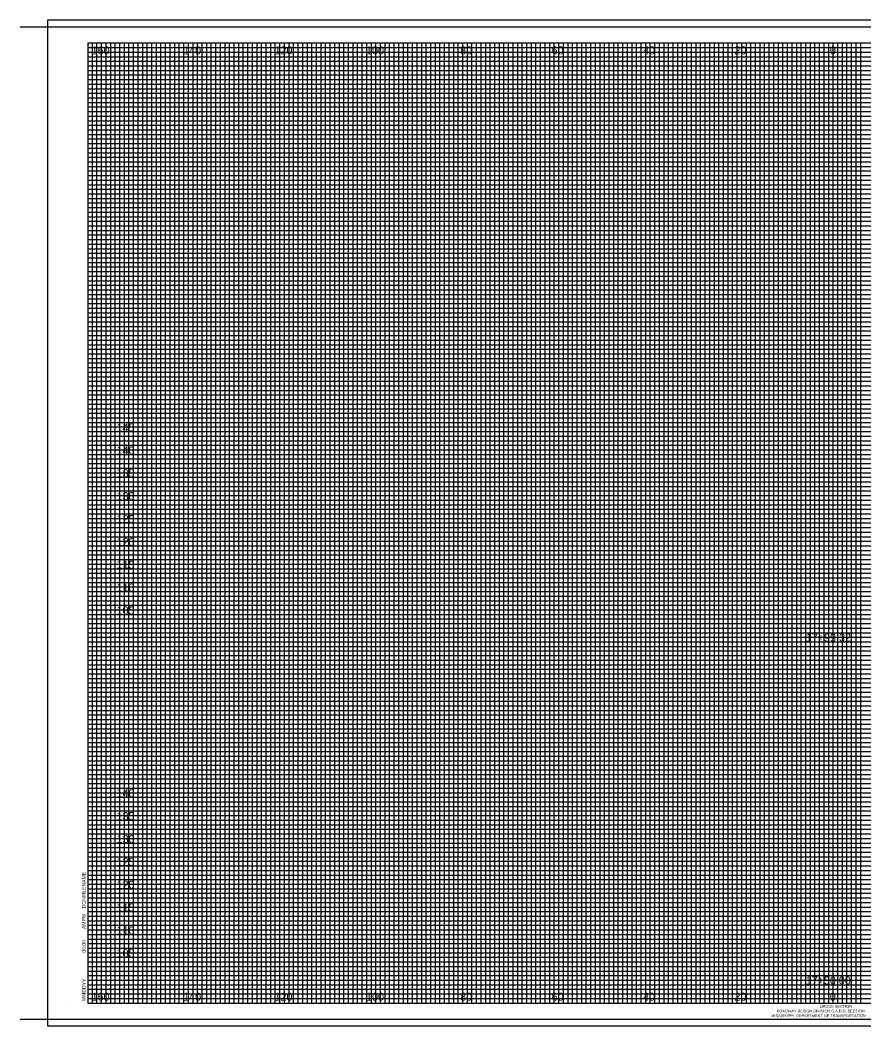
# Model space of a CAD drawing. Extents: x 21281 to 21817, y 6470 to 8300.
# Drawn here: x 21465 to 21649.5, y 8079.8 to 8299.8 of the extents above; entities that cross this region are included whole.
import ezdxf

# ---------------------------------------------------------------- set-up
doc = ezdxf.new("R2010")
doc.units = 0
for name, color, linetype in [('SHEET_BORDER', 7, 'Continuous'), ('SHEET_BORDER_TX', 7, 'Continuous'), ('SHEET_DATE_DGN_TX', 7, 'Continuous'), ('SHEET_PLOTTING_SHAPE', 7, 'Continuous'), ('XS_SHEET_LABELS_ELEVATION', 7, 'Continuous'), ('XS_SHEET_LABELS_OFFSET', 7, 'Continuous'), ('XS_SHEET_LABELS_STATION', 7, 'Continuous'), ('XS_SHEET_MAJOR_GRIDS', 7, 'Continuous'), ('XS_SHEET_MEDIUM_GRIDS', 7, 'Continuous'), ('XS_SHEET_MINOR_GRIDS', 7, 'Continuous')]:
    doc.layers.add(name, color=color, linetype=linetype)

msp = doc.modelspace()

# ---------------------------------------------------------------- linework, layer by layer
at = {"layer": 'SHEET_BORDER'}
for p, q in [((21465.04, 8298.34), (21817.04, 8298.34)), ((21479.84, 8294.84), (21814.84, 8294.84)), ((21479.84, 8294.84), (21479.84, 8084.84)), ((21623.84, 8084.84), (21623.84, 8294.84)), ((21474.84, 8084.84), (21474.84, 8084.84)), ((21479.84, 8084.84), (21814.84, 8084.84)), ((21465.04, 8081.34), (21817.04, 8081.34))]:
    msp.add_line(p, q, dxfattribs=at)
at = {"layer": 'SHEET_PLOTTING_SHAPE'}
msp.add_lwpolyline([(21471.04, 8079.84), (21817.04, 8079.84), (21817.04, 8299.84), (21471.04, 8299.84)], close=True, dxfattribs=at)
at = {"layer": 'XS_SHEET_MAJOR_GRIDS'}
for p, q in [((21484.84, 8084.84), (21484.84, 8294.84)), ((21494.84, 8084.84), (21494.84, 8294.84)), ((21504.84, 8084.84), (21504.84, 8294.84)), ((21514.84, 8084.84), (21514.84, 8294.84)), ((21524.84, 8084.84), (21524.84, 8294.84)), ((21534.84, 8084.84), (21534.84, 8294.84)), ((21544.84, 8084.84), (21544.84, 8294.84)), ((21554.84, 8084.84), (21554.84, 8294.84)), ((21564.84, 8084.84), (21564.84, 8294.84)), ((21574.84, 8084.84), (21574.84, 8294.84)), ((21584.84, 8084.84), (21584.84, 8294.84)), ((21594.84, 8084.84), (21594.84, 8294.84)), ((21604.84, 8084.84), (21604.84, 8294.84)), ((21614.84, 8084.84), (21614.84, 8294.84)), ((21624.84, 8084.84), (21624.84, 8294.84)), ((21634.84, 8084.84), (21634.84, 8294.84)), ((21644.84, 8084.84), (21644.84, 8294.84)), ((21479.84, 8284.84), (21814.84, 8284.84)), ((21479.84, 8274.84), (21814.84, 8274.84)), ((21479.84, 8264.84), (21814.84, 8264.84)), ((21479.84, 8254.84), (21814.84, 8254.84)), ((21479.84, 8244.84), (21814.84, 8244.84)), ((21479.84, 8234.84), (21814.84, 8234.84)), ((21479.84, 8224.84), (21814.84, 8224.84)), ((21479.84, 8214.84), (21814.84, 8214.84)), ((21479.84, 8204.84), (21814.84, 8204.84)), ((21479.84, 8194.84), (21814.84, 8194.84)), ((21479.84, 8184.84), (21814.84, 8184.84)), ((21479.84, 8174.84), (21814.84, 8174.84)), ((21479.84, 8164.84), (21814.84, 8164.84)), ((21479.84, 8154.84), (21814.84, 8154.84)), ((21479.84, 8144.84), (21814.84, 8144.84)), ((21479.84, 8134.84), (21814.84, 8134.84)), ((21479.84, 8124.84), (21814.84, 8124.84)), ((21479.84, 8114.84), (21814.84, 8114.84)), ((21479.84, 8104.84), (21814.84, 8104.84)), ((21479.84, 8094.84), (21814.84, 8094.84))]:
    msp.add_line(p, q, dxfattribs=at)
at = {"layer": 'XS_SHEET_MEDIUM_GRIDS'}
for p, q in [((21489.84, 8084.84), (21489.84, 8294.84)), ((21499.84, 8084.84), (21499.84, 8294.84)), ((21509.84, 8084.84), (21509.84, 8294.84)), ((21519.84, 8084.84), (21519.84, 8294.84)), ((21529.84, 8084.84), (21529.84, 8294.84)), ((21539.84, 8084.84), (21539.84, 8294.84)), ((21549.84, 8084.84), (21549.84, 8294.84)), ((21559.84, 8084.84), (21559.84, 8294.84)), ((21569.84, 8084.84), (21569.84, 8294.84)), ((21579.84, 8084.84), (21579.84, 8294.84)), ((21589.84, 8084.84), (21589.84, 8294.84)), ((21599.84, 8084.84), (21599.84, 8294.84)), ((21609.84, 8084.84), (21609.84, 8294.84)), ((21619.84, 8084.84), (21619.84, 8294.84)), ((21629.84, 8084.84), (21629.84, 8294.84)), ((21639.84, 8084.84), (21639.84, 8294.84)), ((21479.84, 8289.84), (21787.84, 8289.84)), ((21479.84, 8279.84), (21814.84, 8279.84)), ((21479.84, 8269.84), (21814.84, 8269.84)), ((21479.84, 8259.84), (21814.84, 8259.84)), ((21479.84, 8249.84), (21814.84, 8249.84)), ((21479.84, 8239.84), (21814.84, 8239.84)), ((21479.84, 8229.84), (21814.84, 8229.84)), ((21479.84, 8219.84), (21814.84, 8219.84)), ((21479.84, 8209.84), (21814.84, 8209.84)), ((21479.84, 8199.84), (21814.84, 8199.84)), ((21479.84, 8189.84), (21814.84, 8189.84)), ((21479.84, 8179.84), (21814.84, 8179.84)), ((21479.84, 8169.84), (21814.84, 8169.84)), ((21479.84, 8159.84), (21814.84, 8159.84)), ((21479.84, 8149.84), (21814.84, 8149.84)), ((21479.84, 8139.84), (21814.84, 8139.84)), ((21479.84, 8129.84), (21814.84, 8129.84)), ((21479.84, 8119.84), (21814.84, 8119.84)), ((21479.84, 8109.84), (21814.84, 8109.84)), ((21479.84, 8099.84), (21814.84, 8099.84)), ((21479.84, 8089.84), (21804.84, 8089.84))]:
    msp.add_line(p, q, dxfattribs=at)
at = {"layer": 'XS_SHEET_MINOR_GRIDS'}
for p, q in [((21480.84, 8084.84), (21480.84, 8294.84)), ((21481.84, 8084.84), (21481.84, 8294.84)), ((21482.84, 8084.84), (21482.84, 8294.84)), ((21483.84, 8084.84), (21483.84, 8294.84)), ((21485.84, 8084.84), (21485.84, 8294.84)), ((21486.84, 8084.84), (21486.84, 8294.84)), ((21487.84, 8084.84), (21487.84, 8294.84)), ((21488.84, 8084.84), (21488.84, 8294.84)), ((21490.84, 8084.84), (21490.84, 8294.84)), ((21491.84, 8084.84), (21491.84, 8294.84)), ((21492.84, 8084.84), (21492.84, 8294.84)), ((21493.84, 8084.84), (21493.84, 8294.84)), ((21495.84, 8084.84), (21495.84, 8294.84)), ((21496.84, 8084.84), (21496.84, 8294.84)), ((21497.84, 8084.84), (21497.84, 8294.84)), ((21498.84, 8084.84), (21498.84, 8294.84)), ((21500.84, 8084.84), (21500.84, 8294.84)), ((21501.84, 8084.84), (21501.84, 8294.84)), ((21502.84, 8084.84), (21502.84, 8294.84)), ((21503.84, 8084.84), (21503.84, 8294.84)), ((21505.84, 8084.84), (21505.84, 8294.84)), ((21506.84, 8084.84), (21506.84, 8294.84)), ((21507.84, 8084.84), (21507.84, 8294.84)), ((21508.84, 8084.84), (21508.84, 8294.84)), ((21510.84, 8084.84), (21510.84, 8294.84)), ((21511.84, 8084.84), (21511.84, 8294.84)), ((21512.84, 8084.84), (21512.84, 8294.84)), ((21513.84, 8084.84), (21513.84, 8294.84)), ((21515.84, 8084.84), (21515.84, 8294.84)), ((21516.84, 8084.84), (21516.84, 8294.84)), ((21517.84, 8084.84), (21517.84, 8294.84)), ((21518.84, 8084.84), (21518.84, 8294.84)), ((21520.84, 8084.84), (21520.84, 8294.84)), ((21521.84, 8084.84), (21521.84, 8294.84)), ((21522.84, 8084.84), (21522.84, 8294.84)), ((21523.84, 8084.84), (21523.84, 8294.84)), ((21525.84, 8084.84), (21525.84, 8294.84)), ((21526.84, 8084.84), (21526.84, 8294.84)), ((21527.84, 8084.84), (21527.84, 8294.84)), ((21528.84, 8084.84), (21528.84, 8294.84)), ((21530.84, 8084.84), (21530.84, 8294.84)), ((21531.84, 8084.84), (21531.84, 8294.84)), ((21532.84, 8084.84), (21532.84, 8294.84)), ((21533.84, 8084.84), (21533.84, 8294.84)), ((21535.84, 8084.84), (21535.84, 8294.84)), ((21536.84, 8084.84), (21536.84, 8294.84)), ((21537.84, 8084.84), (21537.84, 8294.84)), ((21538.84, 8084.84), (21538.84, 8294.84)), ((21540.84, 8084.84), (21540.84, 8294.84)), ((21541.84, 8084.84), (21541.84, 8294.84)), ((21542.84, 8084.84), (21542.84, 8294.84)), ((21543.84, 8084.84), (21543.84, 8294.84)), ((21545.84, 8084.84), (21545.84, 8294.84)), ((21546.84, 8084.84), (21546.84, 8294.84)), ((21547.84, 8084.84), (21547.84, 8294.84)), ((21548.84, 8084.84), (21548.84, 8294.84)), ((21550.84, 8084.84), (21550.84, 8294.84)), ((21551.84, 8084.84), (21551.84, 8294.84)), ((21552.84, 8084.84), (21552.84, 8294.84)), ((21553.84, 8084.84), (21553.84, 8294.84)), ((21555.84, 8084.84), (21555.84, 8294.84)), ((21556.84, 8084.84), (21556.84, 8294.84)), ((21557.84, 8084.84), (21557.84, 8294.84)), ((21558.84, 8084.84), (21558.84, 8294.84)), ((21560.84, 8084.84), (21560.84, 8294.84)), ((21561.84, 8084.84), (21561.84, 8294.84)), ((21562.84, 8084.84), (21562.84, 8294.84)), ((21563.84, 8084.84), (21563.84, 8294.84)), ((21565.84, 8084.84), (21565.84, 8294.84)), ((21566.84, 8084.84), (21566.84, 8294.84)), ((21567.84, 8084.84), (21567.84, 8294.84)), ((21568.84, 8084.84), (21568.84, 8294.84)), ((21570.84, 8084.84), (21570.84, 8294.84)), ((21571.84, 8084.84), (21571.84, 8294.84)), ((21572.84, 8084.84), (21572.84, 8294.84)), ((21573.84, 8084.84), (21573.84, 8294.84)), ((21575.84, 8084.84), (21575.84, 8294.84)), ((21576.84, 8084.84), (21576.84, 8294.84)), ((21577.84, 8084.84), (21577.84, 8294.84)), ((21578.84, 8084.84), (21578.84, 8294.84)), ((21580.84, 8084.84), (21580.84, 8294.84)), ((21581.84, 8084.84), (21581.84, 8294.84)), ((21582.84, 8084.84), (21582.84, 8294.84)), ((21583.84, 8084.84), (21583.84, 8294.84)), ((21585.84, 8084.84), (21585.84, 8294.84)), ((21586.84, 8084.84), (21586.84, 8294.84)), ((21587.84, 8084.84), (21587.84, 8294.84)), ((21588.84, 8084.84), (21588.84, 8294.84)), ((21590.84, 8084.84), (21590.84, 8294.84)), ((21591.84, 8084.84), (21591.84, 8294.84)), ((21592.84, 8084.84), (21592.84, 8294.84)), ((21593.84, 8084.84), (21593.84, 8294.84)), ((21595.84, 8084.84), (21595.84, 8294.84)), ((21596.84, 8084.84), (21596.84, 8294.84)), ((21597.84, 8084.84), (21597.84, 8294.84)), ((21598.84, 8084.84), (21598.84, 8294.84)), ((21600.84, 8084.84), (21600.84, 8294.84)), ((21601.84, 8084.84), (21601.84, 8294.84)), ((21602.84, 8084.84), (21602.84, 8294.84)), ((21603.84, 8084.84), (21603.84, 8294.84)), ((21605.84, 8084.84), (21605.84, 8294.84)), ((21606.84, 8084.84), (21606.84, 8294.84)), ((21607.84, 8084.84), (21607.84, 8294.84)), ((21608.84, 8084.84), (21608.84, 8294.84)), ((21610.84, 8084.84), (21610.84, 8294.84)), ((21611.84, 8084.84), (21611.84, 8294.84)), ((21612.84, 8084.84), (21612.84, 8294.84)), ((21613.84, 8084.84), (21613.84, 8294.84)), ((21615.84, 8084.84), (21615.84, 8294.84)), ((21616.84, 8084.84), (21616.84, 8294.84)), ((21617.84, 8084.84), (21617.84, 8294.84)), ((21618.84, 8084.84), (21618.84, 8294.84)), ((21620.84, 8084.84), (21620.84, 8294.84)), ((21621.84, 8084.84), (21621.84, 8294.84)), ((21622.84, 8084.84), (21622.84, 8294.84)), ((21625.84, 8084.84), (21625.84, 8294.84)), ((21626.84, 8084.84), (21626.84, 8294.84)), ((21627.84, 8084.84), (21627.84, 8294.84)), ((21628.84, 8084.84), (21628.84, 8294.84)), ((21630.84, 8084.84), (21630.84, 8294.84)), ((21631.84, 8084.84), (21631.84, 8294.84)), ((21632.84, 8084.84), (21632.84, 8294.84)), ((21633.84, 8084.84), (21633.84, 8294.84)), ((21635.84, 8084.84), (21635.84, 8294.84)), ((21636.84, 8084.84), (21636.84, 8294.84)), ((21637.84, 8084.84), (21637.84, 8294.84)), ((21638.84, 8084.84), (21638.84, 8294.84)), ((21640.84, 8084.84), (21640.84, 8294.84)), ((21641.84, 8084.84), (21641.84, 8294.84)), ((21642.84, 8084.84), (21642.84, 8294.84)), ((21643.84, 8084.84), (21643.84, 8294.84)), ((21645.84, 8084.84), (21645.84, 8294.84)), ((21646.84, 8084.84), (21646.84, 8294.84)), ((21647.84, 8084.84), (21647.84, 8294.84)), ((21648.84, 8084.84), (21648.84, 8294.84)), ((21479.84, 8293.84), (21787.84, 8293.84)), ((21479.84, 8292.84), (21787.84, 8292.84)), ((21479.84, 8291.84), (21787.84, 8291.84)), ((21479.84, 8290.84), (21787.84, 8290.84)), ((21479.84, 8288.84), (21787.84, 8288.84)), ((21479.84, 8287.84), (21787.84, 8287.84)), ((21479.84, 8286.84), (21787.84, 8286.84)), ((21479.84, 8285.84), (21814.84, 8285.84)), ((21479.84, 8283.84), (21814.84, 8283.84)), ((21479.84, 8282.84), (21814.84, 8282.84)), ((21479.84, 8281.84), (21814.84, 8281.84)), ((21479.84, 8280.84), (21814.84, 8280.84)), ((21479.84, 8278.84), (21814.84, 8278.84)), ((21479.84, 8277.84), (21814.84, 8277.84)), ((21479.84, 8276.84), (21814.84, 8276.84)), ((21479.84, 8275.84), (21814.84, 8275.84)), ((21479.84, 8273.84), (21814.84, 8273.84)), ((21479.84, 8272.84), (21814.84, 8272.84)), ((21479.84, 8271.84), (21814.84, 8271.84)), ((21479.84, 8270.84), (21814.84, 8270.84)), ((21479.84, 8268.84), (21814.84, 8268.84)), ((21479.84, 8267.84), (21814.84, 8267.84)), ((21479.84, 8266.84), (21814.84, 8266.84)), ((21479.84, 8265.84), (21814.84, 8265.84)), ((21479.84, 8263.84), (21814.84, 8263.84)), ((21479.84, 8262.84), (21814.84, 8262.84)), ((21479.84, 8261.84), (21814.84, 8261.84)), ((21479.84, 8260.84), (21814.84, 8260.84)), ((21479.84, 8258.84), (21814.84, 8258.84)), ((21479.84, 8257.84), (21814.84, 8257.84)), ((21479.84, 8256.84), (21814.84, 8256.84)), ((21479.84, 8255.84), (21814.84, 8255.84)), ((21479.84, 8253.84), (21814.84, 8253.84)), ((21479.84, 8252.84), (21814.84, 8252.84)), ((21479.84, 8251.84), (21814.84, 8251.84)), ((21479.84, 8250.84), (21814.84, 8250.84)), ((21479.84, 8248.84), (21814.84, 8248.84)), ((21479.84, 8247.84), (21814.84, 8247.84)), ((21479.84, 8246.84), (21814.84, 8246.84)), ((21479.84, 8245.84), (21814.84, 8245.84)), ((21479.84, 8243.84), (21814.84, 8243.84)), ((21479.84, 8242.84), (21814.84, 8242.84)), ((21479.84, 8241.84), (21814.84, 8241.84)), ((21479.84, 8240.84), (21814.84, 8240.84)), ((21479.84, 8238.84), (21814.84, 8238.84)), ((21479.84, 8237.84), (21814.84, 8237.84)), ((21479.84, 8236.84), (21814.84, 8236.84)), ((21479.84, 8235.84), (21814.84, 8235.84)), ((21479.84, 8233.84), (21814.84, 8233.84)), ((21479.84, 8232.84), (21814.84, 8232.84)), ((21479.84, 8231.84), (21814.84, 8231.84)), ((21479.84, 8230.84), (21814.84, 8230.84)), ((21479.84, 8228.84), (21814.84, 8228.84)), ((21479.84, 8227.84), (21814.84, 8227.84)), ((21479.84, 8226.84), (21814.84, 8226.84)), ((21479.84, 8225.84), (21814.84, 8225.84)), ((21479.84, 8223.84), (21814.84, 8223.84)), ((21479.84, 8222.84), (21814.84, 8222.84)), ((21479.84, 8221.84), (21814.84, 8221.84)), ((21479.84, 8220.84), (21814.84, 8220.84)), ((21479.84, 8218.84), (21814.84, 8218.84)), ((21479.84, 8217.84), (21814.84, 8217.84)), ((21479.84, 8216.84), (21814.84, 8216.84)), ((21479.84, 8215.84), (21814.84, 8215.84)), ((21479.84, 8213.84), (21814.84, 8213.84)), ((21479.84, 8212.84), (21814.84, 8212.84)), ((21479.84, 8211.84), (21814.84, 8211.84)), ((21479.84, 8210.84), (21814.84, 8210.84)), ((21479.84, 8208.84), (21814.84, 8208.84)), ((21479.84, 8207.84), (21814.84, 8207.84)), ((21479.84, 8206.84), (21814.84, 8206.84)), ((21479.84, 8205.84), (21814.84, 8205.84)), ((21479.84, 8203.84), (21814.84, 8203.84)), ((21479.84, 8202.84), (21814.84, 8202.84)), ((21479.84, 8201.84), (21814.84, 8201.84)), ((21479.84, 8200.84), (21814.84, 8200.84)), ((21479.84, 8198.84), (21814.84, 8198.84)), ((21479.84, 8197.84), (21814.84, 8197.84)), ((21479.84, 8196.84), (21814.84, 8196.84)), ((21479.84, 8195.84), (21814.84, 8195.84)), ((21479.84, 8193.84), (21814.84, 8193.84)), ((21479.84, 8192.84), (21814.84, 8192.84)), ((21479.84, 8191.84), (21814.84, 8191.84)), ((21479.84, 8190.84), (21814.84, 8190.84)), ((21479.84, 8188.84), (21814.84, 8188.84)), ((21479.84, 8187.84), (21814.84, 8187.84)), ((21479.84, 8186.84), (21814.84, 8186.84)), ((21479.84, 8185.84), (21814.84, 8185.84)), ((21479.84, 8183.84), (21814.84, 8183.84)), ((21479.84, 8182.84), (21814.84, 8182.84)), ((21479.84, 8181.84), (21814.84, 8181.84)), ((21479.84, 8180.84), (21814.84, 8180.84)), ((21479.84, 8178.84), (21814.84, 8178.84)), ((21479.84, 8177.84), (21814.84, 8177.84)), ((21479.84, 8176.84), (21814.84, 8176.84)), ((21479.84, 8175.84), (21814.84, 8175.84)), ((21479.84, 8173.84), (21814.84, 8173.84)), ((21479.84, 8172.84), (21814.84, 8172.84)), ((21479.84, 8171.84), (21814.84, 8171.84)), ((21479.84, 8170.84), (21814.84, 8170.84)), ((21479.84, 8168.84), (21814.84, 8168.84)), ((21479.84, 8167.84), (21814.84, 8167.84)), ((21479.84, 8166.84), (21814.84, 8166.84)), ((21479.84, 8165.84), (21814.84, 8165.84)), ((21479.84, 8163.84), (21814.84, 8163.84)), ((21479.84, 8162.84), (21814.84, 8162.84)), ((21479.84, 8161.84), (21814.84, 8161.84)), ((21479.84, 8160.84), (21814.84, 8160.84)), ((21479.84, 8158.84), (21814.84, 8158.84)), ((21479.84, 8157.84), (21814.84, 8157.84)), ((21479.84, 8156.84), (21814.84, 8156.84)), ((21479.84, 8155.84), (21814.84, 8155.84)), ((21479.84, 8153.84), (21814.84, 8153.84)), ((21479.84, 8152.84), (21814.84, 8152.84)), ((21479.84, 8151.84), (21814.84, 8151.84)), ((21479.84, 8150.84), (21814.84, 8150.84)), ((21479.84, 8148.84), (21814.84, 8148.84)), ((21479.84, 8147.84), (21814.84, 8147.84)), ((21479.84, 8146.84), (21814.84, 8146.84)), ((21479.84, 8145.84), (21814.84, 8145.84)), ((21479.84, 8143.84), (21814.84, 8143.84)), ((21479.84, 8142.84), (21814.84, 8142.84)), ((21479.84, 8141.84), (21814.84, 8141.84)), ((21479.84, 8140.84), (21814.84, 8140.84)), ((21479.84, 8138.84), (21814.84, 8138.84)), ((21479.84, 8137.84), (21814.84, 8137.84)), ((21479.84, 8136.84), (21814.84, 8136.84)), ((21479.84, 8135.84), (21814.84, 8135.84)), ((21479.84, 8133.84), (21814.84, 8133.84)), ((21479.84, 8132.84), (21814.84, 8132.84)), ((21479.84, 8131.84), (21814.84, 8131.84)), ((21479.84, 8130.84), (21814.84, 8130.84)), ((21479.84, 8128.84), (21814.84, 8128.84)), ((21479.84, 8127.84), (21814.84, 8127.84)), ((21479.84, 8126.84), (21814.84, 8126.84)), ((21479.84, 8125.84), (21814.84, 8125.84)), ((21479.84, 8123.84), (21814.84, 8123.84)), ((21479.84, 8122.84), (21814.84, 8122.84)), ((21479.84, 8121.84), (21814.84, 8121.84)), ((21479.84, 8120.84), (21814.84, 8120.84)), ((21479.84, 8118.84), (21814.84, 8118.84)), ((21479.84, 8117.84), (21814.84, 8117.84)), ((21479.84, 8116.84), (21814.84, 8116.84)), ((21479.84, 8115.84), (21814.84, 8115.84)), ((21479.84, 8113.84), (21814.84, 8113.84)), ((21479.84, 8112.84), (21814.84, 8112.84)), ((21479.84, 8111.84), (21814.84, 8111.84)), ((21479.84, 8110.84), (21814.84, 8110.84)), ((21479.84, 8108.84), (21814.84, 8108.84)), ((21479.84, 8107.84), (21814.84, 8107.84)), ((21479.84, 8106.84), (21814.84, 8106.84)), ((21479.84, 8105.84), (21814.84, 8105.84)), ((21479.84, 8105.84), (21814.84, 8105.84)), ((21479.84, 8105.84), (21814.84, 8105.84)), ((21479.84, 8103.84), (21814.84, 8103.84)), ((21479.84, 8102.84), (21814.84, 8102.84)), ((21479.84, 8101.84), (21814.84, 8101.84)), ((21479.84, 8100.84), (21814.84, 8100.84)), ((21479.84, 8098.84), (21814.84, 8098.84)), ((21479.84, 8097.84), (21814.84, 8097.84)), ((21479.84, 8096.84), (21814.84, 8096.84)), ((21479.84, 8095.84), (21814.84, 8095.84)), ((21479.84, 8093.84), (21804.84, 8093.84)), ((21479.84, 8092.84), (21804.84, 8092.84)), ((21479.84, 8091.84), (21804.84, 8091.84)), ((21479.84, 8090.84), (21804.84, 8090.84)), ((21479.84, 8090.84), (21804.84, 8090.84)), ((21479.84, 8090.84), (21804.84, 8090.84)), ((21479.84, 8088.84), (21804.84, 8088.84)), ((21479.84, 8087.84), (21804.84, 8087.84)), ((21479.84, 8086.84), (21804.84, 8086.84)), ((21479.84, 8085.84), (21804.84, 8085.84))]:
    msp.add_line(p, q, dxfattribs=at)

# ---------------------------------------------------------------- texts
at = {"layer": 'SHEET_BORDER_TX'}
for s, height, p in [('ROADWAY DESIGN DIVISION C.A.D.D. SECTION', 0.61, (21630.44, 8082.78)), ('CROSS SECTION', 0.62, (21639.87, 8083.81)), ('MISSISSIPPI  DEPARTMENT OF TRANSPORTATION', 0.61, (21629.27, 8081.75))]:
    msp.add_text(s, height=height, dxfattribs=at).set_placement(p)
at = {"layer": 'SHEET_DATE_DGN_TX'}
for s, p in [('DGNFILENAME', (21479.37, 8105.54)), ('AMPM', (21479.37, 8101.02)), ('00:00', (21479.37, 8095.84)), ('MMDDYY', (21479.37, 8085.26))]:
    msp.add_text(s, height=0.8, rotation=90, dxfattribs=at).set_placement(p)
at = {"layer": 'XS_SHEET_LABELS_ELEVATION'}
for s, p in [('  145  ', (21484.84, 8209.84)), ('  140  ', (21484.84, 8204.84)), ('  135  ', (21484.84, 8199.84)), ('  130  ', (21484.84, 8194.84)), ('  125  ', (21484.84, 8189.84)), ('  120  ', (21484.84, 8184.84)), ('  115  ', (21484.84, 8179.84)), ('  110  ', (21484.84, 8174.84)), ('  105  ', (21484.84, 8169.84)), ('  140  ', (21484.84, 8129.84)), ('  135  ', (21484.84, 8124.84)), ('  130  ', (21484.84, 8119.84)), ('  125  ', (21484.84, 8114.84)), ('  120  ', (21484.84, 8109.84)), ('  115  ', (21484.84, 8104.84)), ('  110  ', (21484.84, 8099.84)), ('  105  ', (21484.84, 8094.84))]:
    msp.add_text(s, height=1.75, dxfattribs=at).set_placement(p)
at = {"layer": 'XS_SHEET_LABELS_OFFSET'}
for s, p in [('  160  ', (21479.4, 8292.34)), ('  140  ', (21499.39, 8292.34)), ('  120  ', (21519.39, 8292.34)), ('  100  ', (21539.39, 8292.34)), ('  80  ', (21559.95, 8292.34)), ('  60  ', (21579.97, 8292.34)), ('  40  ', (21599.95, 8292.34)), ('  20  ', (21619.95, 8292.34)), ('  0  ', (21640.81, 8292.34)), ('  0  ', (21640.81, 8292.34)), ('  160  ', (21479.4, 8085.34)), ('  140  ', (21499.39, 8085.34)), ('  120  ', (21519.39, 8085.34)), ('  100  ', (21539.39, 8085.34)), ('  80  ', (21559.95, 8085.34)), ('  60  ', (21579.97, 8085.34)), ('  40  ', (21599.95, 8085.34)), ('  20  ', (21619.95, 8085.34)), ('  0  ', (21640.81, 8085.34)), ('  0  ', (21640.81, 8085.34))]:
    msp.add_text(s, height=1.75, dxfattribs=at).set_placement(p)
at = {"layer": 'XS_SHEET_LABELS_STATION'}
for s, p in [('  17+99.32  ', (21635.57, 8163.89)), ('  17+50.00  ', (21635.54, 8088.89))]:
    msp.add_text(s, height=1.75, dxfattribs=at).set_placement(p)

doc.saveas('drawing.dxf')
